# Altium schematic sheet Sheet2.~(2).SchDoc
size A3
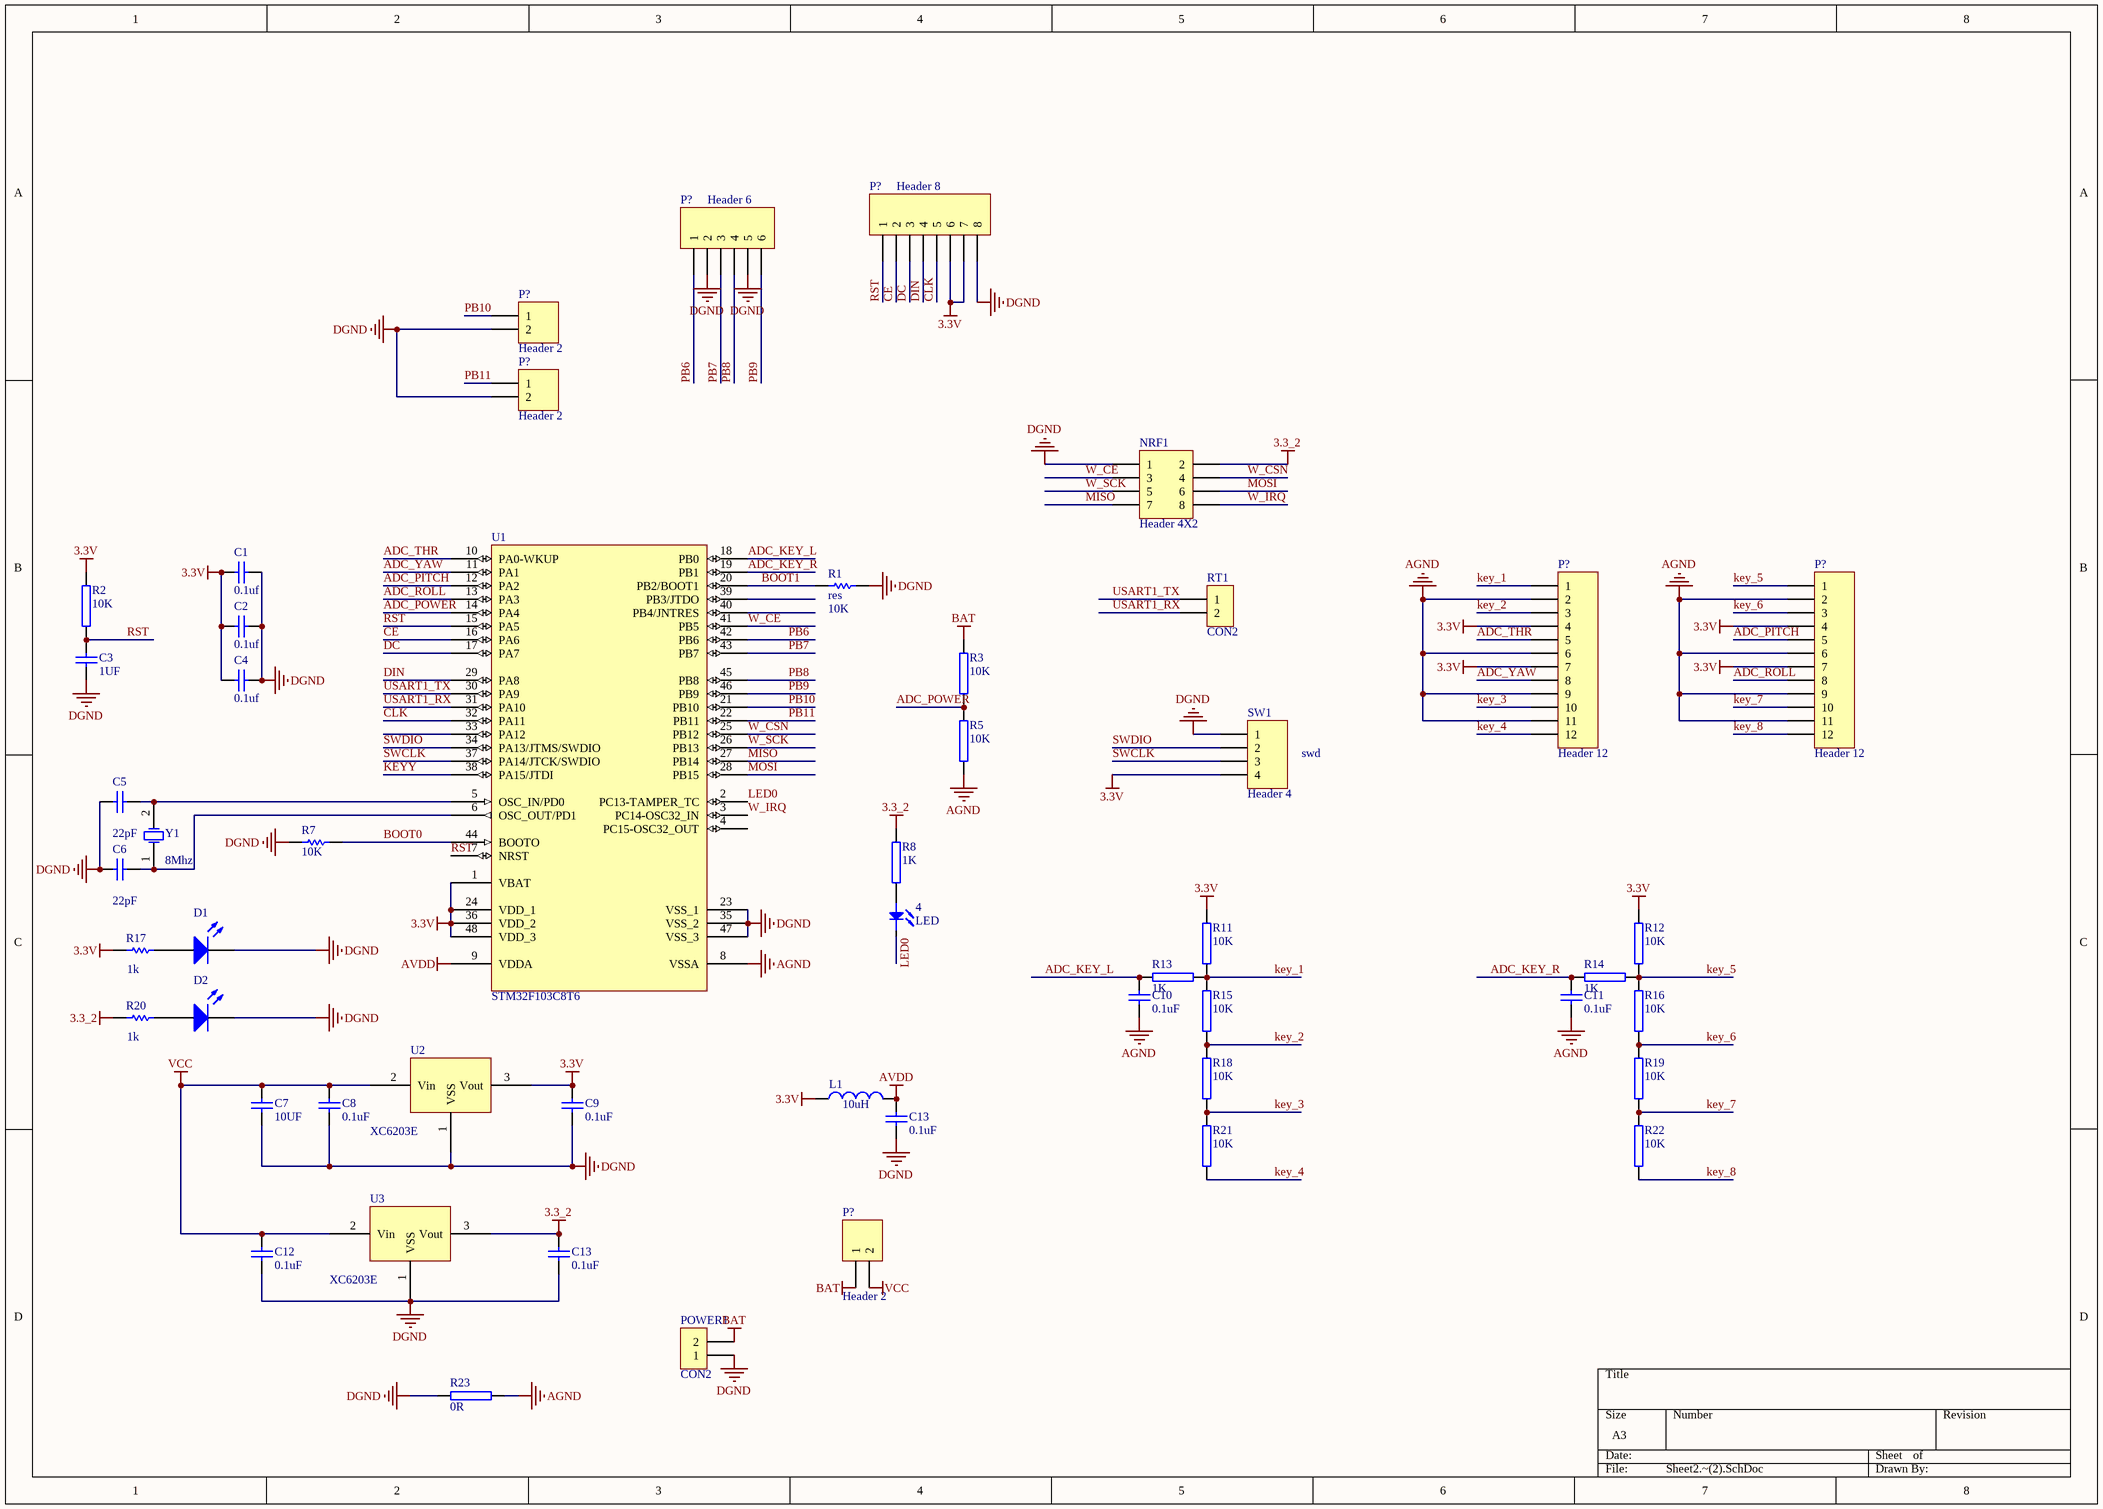
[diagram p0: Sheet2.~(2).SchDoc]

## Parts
(Parts that share a designator on the sheet are numbered #1, #2 ... from top to bottom, then left to right.)
4  LED  [0805]
C1  value 0.1uf  [0805]  (hidden comment: cap)
C2  value 0.1uf  [0805]  (hidden comment: cap)
C3  value 1UF  [0805]  (hidden comment: cap)
C4  value 0.1uf  [0805]  (hidden comment: cap)
C5  value 22pF  [0805]  (hidden comment: cap)
C6  value 22pF  [0805]  (hidden comment: cap)
C7  value 10UF  [0805]  (hidden comment: cap)
C8  value 0.1uF  [0805]  (hidden comment: cap)
C9  value 0.1uF  [0805]  (hidden comment: cap)
C10  value 0.1uF  [0805]  (hidden comment: cap)
C11  value 0.1uF  [0805]  (hidden comment: cap)
C12  value 0.1uF  [0805]  (hidden comment: cap)
C13#1  value 0.1uF  [0805]  (hidden comment: cap)
C13#2  value 0.1uF  [0805]  (hidden comment: cap)
D1  LED0  [0805]  (value not drawn)
D2  LED0  [0805]  (value not drawn)
L1  value 10uH  [0805]  (hidden comment: Inductor)
NRF1  Header 4X2  [HDR2X4]
P?#1  Header 8  [HDR1X8]
P?#2  Header 6  [HDR1X6]
P?#3  Header 2  [HDR1X2]
P?#4  Header 2  [HDR1X2]
P?#5  Header 12  [HDR1X12]
P?#6  Header 12  [HDR1X12]
P?#7  Header 2  [HDR1X2]
POWER1  CON2  [SIP2]
R1  res  res: 10K  [0805]
R2  10K  [0805]
R3  10K  [0805]
R5  10K  [0805]
R7  res: 10K  [0805]  (hidden comment: res)
R8  1K  [0805]
R11  10K  [0805]
R12  10K  [0805]
R13  1K  [0805]
R14  1K  [0805]
R15  10K  [0805]
R16  10K  [0805]
R17  res: 1k  [0805]  (hidden comment: res)
R18  10K  [0805]
R19  10K  [0805]
R20  res: 1k  [0805]  (hidden comment: res)
R21  10K  [0805]
R22  10K  [0805]
R23  0R  [0805]
RT1  CON2  [SIP2]
SW1  Header 4  [HDR1X4]
U1  STM32F103C8T6  [LQFP48S]
U2  XC6203E  [SOT-89]
U3  XC6203E  [SOT-89]
Y1  5032xtal  [XTAL]  (value not drawn)

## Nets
3.3_2: C13#2.2 NRF1.2 R8.2 R20.1 U3.3(Vout)
3.3V: C1.2 C2.2 C4.2 C9.2 L1.1 P?#1.6 P?#1.7 P?#5.4 P?#5.7 P?#6.4 P?#6.7 R2.2 R11.2 R12.2 R17.1 SW1.4 U1.1(VBAT) U1.24(VDD_1) U1.36(VDD_2) U1.48(VDD_3) U2.3(Vout)
AGND: C10.1 C11.1 P?#5.2 P?#5.6 P?#5.9 P?#5.11 P?#6.2 P?#6.6 P?#6.9 P?#6.11 R5.1 R23.2 U1.8(VSSA)
AVDD: C13#1.2 L1.2 U1.9(VDDA)
BAT: P?#7.1 POWER1.2 R3.2
DGND: C1.1 C2.1 C3.1 C4.1 C5.1 C6.1 C7.1 C8.1 C9.1 C12.1 C13#1.1 C13#2.1 D1.2(K) D2.2(K) NRF1.1 P?#1.8 P?#2.2 P?#2.5 P?#3.2 P?#4.2 POWER1.1 R1.2 R7.1 R23.1 SW1.1 U1.23(VSS_1) U1.35(VSS_2) U1.47(VSS_3) U2.1(VSS) U3.1(VSS)
VCC: C7.2 C8.2 C12.2 P?#7.2 U2.2(Vin) U3.2(Vin)
ADC_KEY_L: C10.2 R13.2 U1.18(PB0)
ADC_KEY_R: C11.2 R14.2 U1.19(PB1)
ADC_PITCH: P?#6.5 U1.12(PA2)
ADC_POWER: R3.1 R5.2 U1.14(PA4)
ADC_ROLL: P?#6.8 U1.13(PA3)
ADC_THR: P?#5.5 U1.10(PA0-WKUP)
ADC_YAW: P?#5.8 U1.11(PA1)
BOOT0: R7.2 U1.44(BOOTO)
BOOT1: R1.1 U1.20(PB2/BOOT1)
CE: P?#1.2 U1.16(PA6)
CLK: P?#1.5 U1.32(PA11)
DC: P?#1.3 U1.17(PA7)
DIN: P?#1.4 U1.29(PA8)
key_1: P?#5.1 R11.1 R13.1 R15.2
key_2: P?#5.3 R15.1 R18.2
key_3: P?#5.10 R18.1 R21.2
key_4: P?#5.12 R21.1
key_5: P?#6.1 R12.1 R14.1 R16.2
key_6: P?#6.3 R16.1 R19.2
key_7: P?#6.10 R19.1 R22.2
key_8: P?#6.12 R22.1
KEYY: U1.38(PA15/JTDI)
LED0: 4.K U1.2(PC13-TAMPER_TC)
MISO: NRF1.7 U1.27(PB14)
MOSI: NRF1.6 U1.28(PB15)
PB6: P?#2.1 U1.42(PB6)
PB7: P?#2.3 U1.43(PB7)
PB8: P?#2.4 U1.45(PB8)
PB9: P?#2.6 U1.46(PB9)
PB10: P?#3.1 U1.21(PB10)
PB11: P?#4.1 U1.22(PB11)
RST: C3.2 P?#1.1 R2.1 U1.7(NRST) U1.15(PA5)
SWCLK: SW1.3 U1.37(PA14/JTCK/SWDIO)
SWDIO: SW1.2 U1.34(PA13/JTMS/SWDIO)
USART1_RX: RT1.2 U1.31(PA10)
USART1_TX: RT1.1 U1.30(PA9)
W_CE: NRF1.3 U1.41(PB5)
W_CSN: NRF1.4 U1.25(PB12)
W_IRQ: NRF1.8 U1.3(PC14-OSC32_IN)
W_SCK: NRF1.5 U1.26(PB13)
Net4_A: 4.A R8.1
NetC5_2: C5.2 U1.5(OSC_IN/PD0) Y1.2(OSC2)
NetC6_2: C6.2 U1.6(OSC_OUT/PD1) Y1.1(OSC1)
NetD1_1: D1.1(A) R17.2
NetD2_1: D2.1(A) R20.2

Not connected (* = marked no-connect by the designer): U1 4(PC15-OSC32_OUT) 33(PA12) 39(PB3/JTDO) 40(PB4/JNTRES)

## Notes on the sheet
- swd

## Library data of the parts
4 = LED: pin to pad: A>1 K>2
D1 D2 = LED0: Typical INFRARED GaAs LED
NRF1 = Header 4X2: Header, 4-Pin, Dual row
P?#1 = Header 8: Header, 8-Pin
P?#2 = Header 6: Header, 6-Pin
P?#3 P?#4 P?#7 = Header 2: Header, 2-Pin
P?#5 P?#6 = Header 12: Header, 12-Pin
R2 R3 R5 R8 R11-R16 R18 R19 R21-R23 = RES
SW1 = Header 4: Header, 4-Pin
U2 U3 = XC6203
